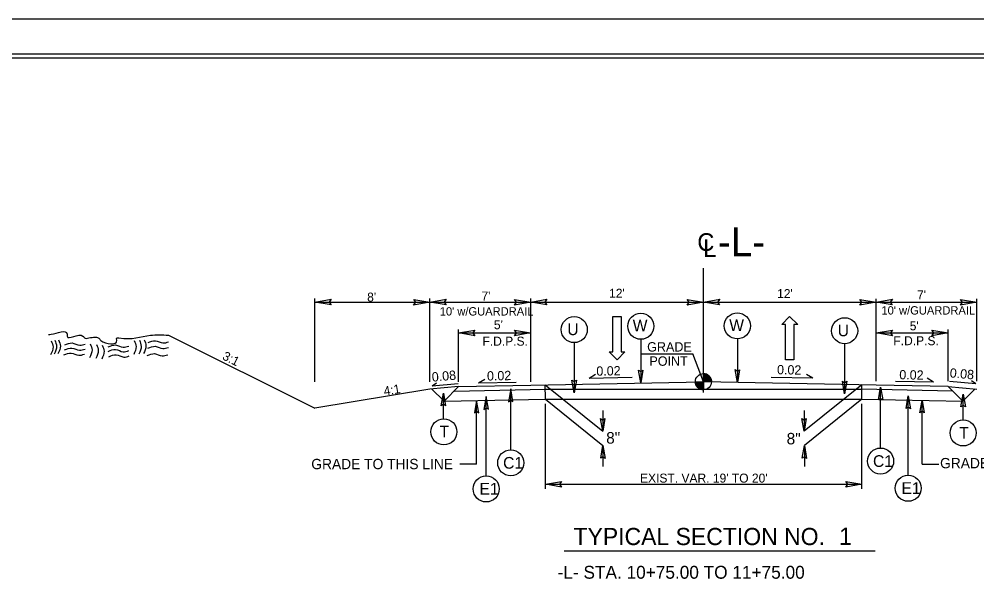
# Model space of a CAD drawing. Extents: x 1733676 to 1734289, y 540979 to 541226.
# Drawn here: x 1734169.6 to 1734236.1, y 541186.7 to 541225.9 of the extents above; entities that cross this region are included whole.
import ezdxf

# ---------------------------------------------------------------- set-up
doc = ezdxf.new("R2010")
doc.units = 0
for name, color, linetype in [('Old_Level_2', 7, 'Continuous'), ('Prop Dimension', 7, 'Continuous'), ('Prop Lane Arrow CELL', 7, 'Continuous'), ('Prop Terminator CELL', 7, 'Continuous'), ('Sheet Cutting Line CELL', 7, 'Continuous'), ('Sheet Plot Border Inside CELL', 7, 'Continuous'), ('Sheet Plot Border Outside CELL', 7, 'Continuous'), ('Sheet Typical CELL', 7, 'Continuous'), ('Typical Grade Point Symbol CELL', 7, 'Continuous'), ('Typical ID Circle CELL', 7, 'Continuous'), ('Typical Pavement Slope CELL', 7, 'Continuous'), ('Typical Pavement Slope Information CELL', 7, 'Continuous'), ('Typical Shoulder Slope CELL', 7, 'Continuous'), ('Typical Shoulder Slope Information CELL', 7, 'Continuous'), ('Typical Slope Point Local CELL', 7, 'Continuous'), ('Typical Terminator CELL', 7, 'Continuous'), ('Typical Text Centerline CELL', 7, 'Continuous'), ('Typical Text General CELL', 7, 'Continuous'), ('Typical Text Grade Point CELL', 7, 'Continuous'), ('Typical Text ID Circle CELL', 7, 'Continuous'), ('Typical Text Label CELL', 7, 'Continuous')]:
    doc.layers.add(name, color=color, linetype=linetype)

msp = doc.modelspace()

# ---------------------------------------------------------------- linework, layer by layer
at = {"layer": 'Old_Level_2'}
for points in [[(1734171.638, 541203.962), (1734171.824, 541203.984), (1734172.92, 541203.997), (1734172.922, 541203.84), (1734174.019, 541203.853), (1734174.177, 541203.698), (1734174.334, 541203.7), (1734175.117, 541203.709), (1734175.275, 541203.554), (1734176.372, 541203.567), (1734176.37, 541203.724), (1734176.526, 541203.726), (1734178.717, 541203.908), (1734179.966, 541203.922)], [(1734171.821, 541203.523), (1734171.948, 541203.104), (1734171.779, 541202.558)], [(1734172.066, 541203.561), (1734172.194, 541203.141), (1734172.024, 541202.595)], [(1734172.329, 541203.582), (1734172.456, 541203.162), (1734172.287, 541202.616)], [(1734172.749, 541202.893), (1734173.257, 541203.022), (1734173.785, 541202.87), (1734174.17, 541202.945)], [(1734172.763, 541203.245), (1734173.27, 541203.373), (1734173.798, 541203.221), (1734174.183, 541203.296)], [(1734174.525, 541203.309), (1734174.653, 541202.889), (1734174.484, 541202.343)], [(1734174.964, 541203.261), (1734175.092, 541202.842), (1734174.923, 541202.296)], [(1734175.368, 541203.213), (1734175.496, 541202.794), (1734175.327, 541202.248)], [(1734175.782, 541203.104), (1734176.289, 541203.233), (1734176.817, 541203.081), (1734177.203, 541203.155)], [(1734177.593, 541203.537), (1734177.72, 541203.118), (1734177.551, 541202.572)], [(1734177.943, 541203.559), (1734178.071, 541203.139), (1734177.902, 541202.593)], [(1734178.276, 541203.598), (1734178.404, 541203.178), (1734178.235, 541202.632)], [(1734178.538, 541203.013), (1734179.045, 541203.142), (1734179.573, 541202.99), (1734179.958, 541203.065)], [(1734178.551, 541203.399), (1734179.058, 541203.528), (1734179.586, 541203.376), (1734179.971, 541203.451)], [(1734172.701, 541202.542), (1734173.208, 541202.671), (1734173.736, 541202.519), (1734174.121, 541202.593)], [(1734175.786, 541202.788), (1734176.293, 541202.917), (1734176.821, 541202.765), (1734177.206, 541202.84)], [(1734175.825, 541202.42), (1734176.332, 541202.549), (1734176.86, 541202.397), (1734177.246, 541202.472)], [(1734178.491, 541202.504), (1734178.998, 541202.632), (1734179.526, 541202.481), (1734179.912, 541202.555)]]:
    msp.add_spline(points, degree=3, dxfattribs=at)
at = {"layer": 'Prop Dimension'}
for p, q in [((1734217.135, 541199.924), (1734217.135, 541208.57)), ((1734190.135, 541200.683), (1734190.135, 541206.461)), ((1734198.135, 541200.683), (1734198.135, 541206.461)), ((1734205.135, 541200.683), (1734205.135, 541206.461)), ((1734229.135, 541200.71), (1734229.135, 541206.434)), ((1734236.135, 541200.71), (1734236.135, 541206.434)), ((1734190.135, 541206.211), (1734198.135, 541206.211)), ((1734198.135, 541206.211), (1734205.135, 541206.211)), ((1734205.135, 541206.211), (1734217.135, 541206.211)), ((1734217.135, 541206.211), (1734229.135, 541206.211)), ((1734229.135, 541206.211), (1734236.135, 541206.211)), ((1734200.13, 541200.682), (1734200.13, 541204.32)), ((1734200.13, 541204.07), (1734205.13, 541204.07)), ((1734229.139, 541204.07), (1734234.135, 541204.07)), ((1734234.135, 541200.71), (1734234.135, 541204.32)), ((1734212.862, 541202.62), (1734216.4, 541202.62)), ((1734217.135, 541200.683), (1734216.4, 541202.62)), ((1734206.135, 541200.463), (1734210.136, 541197.239)), ((1734228.135, 541200.463), (1734224.134, 541197.239)), ((1734206.155, 541200.162), (1734228.155, 541200.162)), ((1734228.155, 541199.462), (1734228.155, 541200.143)), ((1734206.155, 541199.463), (1734228.155, 541199.462)), ((1734206.155, 541199.463), (1734210.156, 541196.24)), ((1734206.155, 541193.241), (1734206.155, 541199.146)), ((1734228.155, 541199.462), (1734224.154, 541196.239)), ((1734228.155, 541193.241), (1734228.155, 541199.146)), ((1734210.136, 541198.692), (1734210.136, 541197.239)), ((1734224.134, 541198.692), (1734224.134, 541197.239)), ((1734210.156, 541196.24), (1734210.156, 541194.787)), ((1734224.154, 541196.239), (1734224.154, 541194.786)), ((1734201.378, 541194.947), (1734200.206, 541194.947)), ((1734232.325, 541194.946), (1734233.498, 541194.946)), ((1734206.155, 541193.555), (1734228.155, 541193.555))]:
    msp.add_line(p, q, dxfattribs=at)
at = {"layer": 'Prop Lane Arrow CELL'}
for p, q in [((1734210.838, 541202.758), (1734210.838, 541205.208)), ((1734210.838, 541205.208), (1734211.416, 541205.208)), ((1734211.416, 541205.208), (1734211.416, 541202.758)), ((1734222.583, 541204.656), (1734223.126, 541205.207)), ((1734223.126, 541205.207), (1734223.686, 541204.656)), ((1734222.846, 541204.656), (1734222.583, 541204.656)), ((1734222.846, 541202.206), (1734222.846, 541204.656)), ((1734223.686, 541204.656), (1734223.423, 541204.656)), ((1734223.423, 541204.656), (1734223.423, 541202.206)), ((1734211.136, 541202.207), (1734210.576, 541202.758)), ((1734210.576, 541202.758), (1734210.838, 541202.758)), ((1734211.678, 541202.758), (1734211.136, 541202.207)), ((1734211.416, 541202.758), (1734211.678, 541202.758)), ((1734223.423, 541202.206), (1734222.846, 541202.206))]:
    msp.add_line(p, q, dxfattribs=at)
at = {"layer": 'Prop Terminator CELL'}
for points in [[(1734191.26, 541206.018), (1734190.135, 541206.211), (1734191.266, 541206.411), (1734191.122, 541206.211)], [(1734197.01, 541206.405), (1734198.135, 541206.211), (1734197.003, 541206.011), (1734197.147, 541206.211)], [(1734199.26, 541206.018), (1734198.135, 541206.211), (1734199.266, 541206.411), (1734199.122, 541206.211)], [(1734204.01, 541206.405), (1734205.135, 541206.211), (1734204.003, 541206.011), (1734204.147, 541206.211)], [(1734206.26, 541206.018), (1734205.135, 541206.211), (1734206.266, 541206.411), (1734206.122, 541206.211)], [(1734216.01, 541206.405), (1734217.135, 541206.211), (1734216.003, 541206.011), (1734216.147, 541206.211)], [(1734218.26, 541206.018), (1734217.135, 541206.211), (1734218.266, 541206.411), (1734218.122, 541206.211)], [(1734228.01, 541206.405), (1734229.135, 541206.211), (1734228.003, 541206.011), (1734228.147, 541206.211)], [(1734230.26, 541206.018), (1734229.135, 541206.211), (1734230.266, 541206.411), (1734230.122, 541206.211)], [(1734235.01, 541206.405), (1734236.135, 541206.211), (1734235.003, 541206.011), (1734235.147, 541206.211)], [(1734201.255, 541203.876), (1734200.13, 541204.07), (1734201.262, 541204.27), (1734201.118, 541204.07)], [(1734204.005, 541204.264), (1734205.13, 541204.07), (1734203.999, 541203.87), (1734204.143, 541204.07)], [(1734230.264, 541203.876), (1734229.139, 541204.07), (1734230.27, 541204.27), (1734230.127, 541204.07)], [(1734233.01, 541204.264), (1734234.135, 541204.07), (1734233.003, 541203.87), (1734233.147, 541204.07)], [(1734201.524, 541198.525), (1734201.378, 541199.369), (1734201.228, 541198.521), (1734201.378, 541198.628)], [(1734232.18, 541198.524), (1734232.325, 541199.368), (1734232.475, 541198.519), (1734232.325, 541198.627)], [(1734207.28, 541193.361), (1734206.155, 541193.555), (1734207.286, 541193.755), (1734207.142, 541193.555)], [(1734227.03, 541193.749), (1734228.155, 541193.555), (1734227.023, 541193.355), (1734227.167, 541193.555)]]:
    msp.add_lwpolyline(points, close=True, dxfattribs=at)
at = {"layer": 'Sheet Cutting Line CELL'}
msp.add_line((1734266.513, 541225.875), (1734084.641, 541225.875), dxfattribs=at)
at = {"layer": 'Sheet Plot Border Inside CELL'}
msp.add_lwpolyline([(1734266.027, 541223.451), (1734086.045, 541223.451), (1734086.045, 541109.5), (1734266.027, 541109.5)], close=True, dxfattribs=at)
at = {"layer": 'Sheet Plot Border Outside CELL'}
msp.add_lwpolyline([(1734266.513, 541225.875), (1734084.641, 541225.875), (1734084.641, 541107.075), (1734266.513, 541107.075)], close=True, dxfattribs=at)
at = {"layer": 'Sheet Typical CELL'}
msp.add_lwpolyline([(1734264.677, 541223.175), (1734102.677, 541223.175), (1734102.677, 541109.775), (1734264.677, 541109.775)], close=True, dxfattribs=at)
at = {"layer": 'Typical Grade Point Symbol CELL'}
for p, q in [((1734217.135, 541200.683), (1734217.135, 541201.242)), ((1734216.575, 541200.683), (1734217.135, 541200.683)), ((1734217.133, 541200.123), (1734217.135, 541200.683)), ((1734217.135, 541200.683), (1734217.133, 541200.123)), ((1734217.694, 541200.683), (1734217.135, 541200.683))]:
    msp.add_line(p, q, dxfattribs=at)
for points in [[(1734217.14, 541201.242), (1734217.14, 541201.242), (1734217.14, 541200.683)], [(1734217.151, 541201.242), (1734217.151, 541200.683)], [(1734217.162, 541201.241), (1734217.162, 541200.683)], [(1734217.173, 541201.241), (1734217.173, 541200.683)], [(1734217.184, 541201.24), (1734217.184, 541200.683)], [(1734217.196, 541201.238), (1734217.196, 541200.683)], [(1734217.207, 541201.237), (1734217.207, 541200.683)], [(1734217.218, 541201.236), (1734217.218, 541200.683)], [(1734217.229, 541201.235), (1734217.229, 541200.683)], [(1734217.24, 541201.232), (1734217.24, 541200.683)], [(1734217.252, 541201.23), (1734217.252, 541200.683)], [(1734217.263, 541201.227), (1734217.263, 541200.683)], [(1734217.274, 541201.225), (1734217.274, 541200.683)], [(1734217.285, 541201.221), (1734217.285, 541200.683)], [(1734217.296, 541201.218), (1734217.296, 541200.683)], [(1734217.308, 541201.215), (1734217.308, 541200.683)], [(1734217.319, 541201.211), (1734217.319, 541200.683)], [(1734217.33, 541201.207), (1734217.33, 541200.683)], [(1734217.341, 541201.202), (1734217.341, 541200.683)], [(1734217.352, 541201.197), (1734217.352, 541200.683)], [(1734217.364, 541201.192), (1734217.364, 541200.683)], [(1734217.375, 541201.187), (1734217.375, 541200.683)], [(1734217.386, 541201.182), (1734217.386, 541200.683)], [(1734217.397, 541201.176), (1734217.397, 541200.683)], [(1734217.408, 541201.17), (1734217.408, 541200.683)], [(1734217.419, 541201.164), (1734217.419, 541200.683)], [(1734217.431, 541201.158), (1734217.431, 541200.683)], [(1734217.442, 541201.15), (1734217.442, 541200.683)], [(1734217.453, 541201.143), (1734217.453, 541200.683)], [(1734217.464, 541201.134), (1734217.464, 541200.683)], [(1734217.475, 541201.126), (1734217.475, 541200.683)], [(1734217.487, 541201.118), (1734217.487, 541200.683)], [(1734217.498, 541201.108), (1734217.498, 541200.683)], [(1734217.509, 541201.098), (1734217.509, 541200.683)], [(1734217.52, 541201.088), (1734217.52, 541200.683)], [(1734217.531, 541201.077), (1734217.531, 541200.683)], [(1734217.543, 541201.066), (1734217.543, 541200.683)], [(1734217.554, 541201.053), (1734217.554, 541200.683)], [(1734217.565, 541201.039), (1734217.565, 541200.683)], [(1734217.576, 541201.026), (1734217.576, 541200.683)], [(1734217.587, 541201.011), (1734217.587, 541200.683)], [(1734216.578, 541200.683), (1734216.578, 541200.622)], [(1734216.589, 541200.683), (1734216.589, 541200.556)], [(1734216.6, 541200.683), (1734216.6, 541200.516)], [(1734216.611, 541200.683), (1734216.611, 541200.482)], [(1734216.623, 541200.683), (1734216.623, 541200.456)], [(1734216.634, 541200.683), (1734216.634, 541200.433)], [(1734216.645, 541200.683), (1734216.645, 541200.412)], [(1734216.656, 541200.683), (1734216.656, 541200.392)], [(1734216.667, 541200.683), (1734216.667, 541200.374)], [(1734216.678, 541200.683), (1734216.678, 541200.358)], [(1734216.69, 541200.683), (1734216.69, 541200.343)], [(1734216.701, 541200.683), (1734216.701, 541200.329)], [(1734216.712, 541200.683), (1734216.712, 541200.316)], [(1734216.723, 541200.683), (1734216.723, 541200.303)], [(1734216.734, 541200.683), (1734216.734, 541200.291)], [(1734216.746, 541200.683), (1734216.746, 541200.28)], [(1734216.757, 541200.683), (1734216.757, 541200.27)], [(1734216.768, 541200.683), (1734216.768, 541200.26)], [(1734216.779, 541200.683), (1734216.779, 541200.25)], [(1734216.79, 541200.683), (1734216.79, 541200.241)], [(1734216.802, 541200.683), (1734216.802, 541200.233)], [(1734216.813, 541200.683), (1734216.813, 541200.225)], [(1734216.824, 541200.683), (1734216.824, 541200.218)], [(1734216.835, 541200.683), (1734216.835, 541200.21)], [(1734216.846, 541200.683), (1734216.846, 541200.203)], [(1734216.857, 541200.683), (1734216.857, 541200.196)], [(1734216.869, 541200.683), (1734216.869, 541200.19)], [(1734216.88, 541200.683), (1734216.88, 541200.184)], [(1734216.891, 541200.683), (1734216.891, 541200.179)], [(1734216.902, 541200.683), (1734216.902, 541200.174)], [(1734216.913, 541200.683), (1734216.913, 541200.169)], [(1734216.925, 541200.683), (1734216.925, 541200.164)], [(1734216.936, 541200.683), (1734216.936, 541200.159)], [(1734216.947, 541200.683), (1734216.947, 541200.155)], [(1734216.958, 541200.683), (1734216.958, 541200.152)], [(1734216.969, 541200.683), (1734216.969, 541200.148)], [(1734216.981, 541200.683), (1734216.981, 541200.145)], [(1734216.992, 541200.683), (1734216.992, 541200.142)], [(1734217.003, 541200.683), (1734217.003, 541200.139)], [(1734217.014, 541200.683), (1734217.014, 541200.137)], [(1734217.025, 541200.683), (1734217.025, 541200.134)], [(1734217.036, 541200.683), (1734217.036, 541200.132)], [(1734217.048, 541200.683), (1734217.048, 541200.131)], [(1734217.059, 541200.683), (1734217.059, 541200.128)], [(1734217.07, 541200.683), (1734217.07, 541200.127)], [(1734217.081, 541200.683), (1734217.081, 541200.126)], [(1734217.092, 541200.683), (1734217.092, 541200.124)], [(1734217.104, 541200.683), (1734217.104, 541200.124)], [(1734217.115, 541200.683), (1734217.115, 541200.123)], [(1734217.126, 541200.683), (1734217.126, 541200.123), (1734217.126, 541200.123)], [(1734217.599, 541200.995), (1734217.599, 541200.683)], [(1734217.61, 541200.977), (1734217.61, 541200.683)], [(1734217.621, 541200.959), (1734217.621, 541200.683)], [(1734217.632, 541200.939), (1734217.632, 541200.683)], [(1734217.643, 541200.915), (1734217.643, 541200.683)], [(1734217.654, 541200.889), (1734217.654, 541200.683)], [(1734217.666, 541200.858), (1734217.666, 541200.683)], [(1734217.677, 541200.819), (1734217.677, 541200.683)], [(1734217.688, 541200.762), (1734217.688, 541200.683)]]:
    msp.add_lwpolyline(points, dxfattribs=at)
msp.add_circle((1734217.134, 541200.683), 0.559, dxfattribs=at)
for start, end in [(359.99048, 89.99048), (179.99048, 269.99048)]:
    msp.add_arc((1734217.134, 541200.683), 0.559, start, end, dxfattribs=at)
at = {"layer": 'Typical ID Circle CELL'}
for p, q in [((1734208.16, 541203.396), (1734208.16, 541199.914)), ((1734212.786, 541203.63), (1734212.786, 541200.609)), ((1734219.493, 541203.656), (1734219.493, 541200.636)), ((1734226.949, 541203.316), (1734226.949, 541199.834)), ((1734199.068, 541198.102), (1734199.068, 541199.882)), ((1734203.748, 541195.951), (1734203.748, 541200.178)), ((1734229.449, 541196.073), (1734229.449, 541200.298)), ((1734231.365, 541194.186), (1734231.365, 541199.692)), ((1734235.181, 541198.029), (1734235.181, 541199.808)), ((1734201.378, 541194.947), (1734201.378, 541199.369)), ((1734202.043, 541194.139), (1734202.043, 541199.644)), ((1734232.325, 541194.946), (1734232.325, 541199.368))]:
    msp.add_line(p, q, dxfattribs=at)
for centre in [(1734208.16, 541204.303), (1734212.786, 541204.536), (1734219.493, 541204.563), (1734226.949, 541204.222), (1734199.101, 541197.197), (1734235.181, 541197.123), (1734203.748, 541195.045), (1734229.449, 541195.167), (1734202.043, 541193.232), (1734231.365, 541193.279)]:
    msp.add_circle(centre, 0.906, dxfattribs=at)
at = {"layer": 'Typical Pavement Slope CELL'}
for p, q in [((1734200.13, 541200.34), (1734198.13, 541200.173)), ((1734205.135, 541200.443), (1734217.135, 541200.683)), ((1734206.155, 541199.463), (1734206.135, 541200.463)), ((1734229.135, 541200.443), (1734217.135, 541200.683)), ((1734228.155, 541199.462), (1734228.155, 541200.462)), ((1734234.135, 541200.34), (1734236.135, 541200.173)), ((1734199.112, 541199.322), (1734206.155, 541199.463)), ((1734228.155, 541199.462), (1734235.153, 541199.322))]:
    msp.add_line(p, q, dxfattribs=at)
at = {"layer": 'Typical Pavement Slope Information CELL'}
for p, q in [((1734209.202, 541200.939), (1734209.639, 541201.203)), ((1734209.202, 541200.939), (1734212.193, 541200.999)), ((1734224.745, 541200.917), (1734224.296, 541201.189)), ((1734198.293, 541200.394), (1734198.585, 541200.599)), ((1734198.293, 541200.394), (1734200.101, 541200.556)), ((1734201.518, 541200.596), (1734201.956, 541200.86)), ((1734201.518, 541200.596), (1734204.118, 541200.648)), ((1734224.745, 541200.917), (1734221.851, 541200.975)), ((1734233.133, 541200.646), (1734230.493, 541200.699)), ((1734233.133, 541200.646), (1734232.684, 541200.918)), ((1734236.066, 541200.542), (1734234.228, 541200.697)), ((1734236.066, 541200.542), (1734235.765, 541200.752))]:
    msp.add_line(p, q, dxfattribs=at)
at = {"layer": 'Typical Shoulder Slope CELL'}
for p, q in [((1734200.13, 541200.34), (1734199.112, 541199.321)), ((1734200.13, 541200.34), (1734205.135, 541200.443)), ((1734234.135, 541200.34), (1734229.135, 541200.443)), ((1734234.135, 541200.34), (1734235.153, 541199.321)), ((1734198.25, 541200.183), (1734199.112, 541199.321)), ((1734199.824, 541200.034), (1734206.155, 541200.163)), ((1734234.441, 541200.034), (1734228.155, 541200.163)), ((1734236.015, 541200.183), (1734235.153, 541199.321))]:
    msp.add_line(p, q, dxfattribs=at)
at = {"layer": 'Typical Slope Point Local CELL'}
for p in [(1734179.966, 541203.922), (1734198.13, 541200.173)]:
    msp.add_line(p, (1734190.13, 541198.84), dxfattribs=at)
at = {"layer": 'Typical Terminator CELL'}
for points in [[(1734212.938, 541201.488), (1734212.786, 541200.609), (1734212.63, 541201.493), (1734212.786, 541201.381)], [(1734219.644, 541201.515), (1734219.493, 541200.636), (1734219.337, 541201.52), (1734219.493, 541201.407)], [(1734208.312, 541200.793), (1734208.16, 541199.914), (1734208.004, 541200.798), (1734208.16, 541200.686)], [(1734227.1, 541200.713), (1734226.949, 541199.834), (1734226.793, 541200.718), (1734226.949, 541200.605)], [(1734198.917, 541199.003), (1734199.068, 541199.882), (1734199.224, 541198.998), (1734199.068, 541199.111)], [(1734203.9, 541199.299), (1734203.748, 541200.178), (1734203.592, 541199.294), (1734203.748, 541199.407)], [(1734229.298, 541199.419), (1734229.449, 541200.298), (1734229.605, 541199.414), (1734229.449, 541199.526)], [(1734231.213, 541198.813), (1734231.365, 541199.692), (1734231.521, 541198.808), (1734231.365, 541198.92)], [(1734235.03, 541198.93), (1734235.181, 541199.808), (1734235.337, 541198.925), (1734235.181, 541199.037)], [(1734202.195, 541198.766), (1734202.043, 541199.644), (1734201.887, 541198.761), (1734202.043, 541198.873)], [(1734210.287, 541198.118), (1734210.136, 541197.239), (1734209.98, 541198.123), (1734210.136, 541198.011)], [(1734224.285, 541198.118), (1734224.134, 541197.239), (1734223.977, 541198.123), (1734224.134, 541198.011)], [(1734210.005, 541195.361), (1734210.156, 541196.24), (1734210.312, 541195.356), (1734210.156, 541195.468)], [(1734224.002, 541195.36), (1734224.154, 541196.239), (1734224.31, 541195.355), (1734224.154, 541195.467)]]:
    msp.add_lwpolyline(points, close=True, dxfattribs=at)
at = {"layer": 'Typical Text Label CELL'}
msp.add_line((1734207.469, 541188.929), (1734229.073, 541188.929), dxfattribs=at)

# ---------------------------------------------------------------- texts
at = {"layer": 'Typical Pavement Slope Information CELL'}
for rotation, p in [(1.14574, (1734209.703, 541201.094)), (358.85426, (1734222.248, 541201.202))]:
    msp.add_text('0.02', height=0.6476, rotation=rotation, dxfattribs=at).set_placement(p)
at = {"layer": 'Typical Shoulder Slope Information CELL'}
for s, rotation, p in [('0.08', 5.10489, (1734198.293, 541200.68)), ('0.02', 1.14574, (1734202.103, 541200.76)), ('0.02', 358.85426, (1734230.742, 541200.852)), ('0.08', 355.18719, (1734234.232, 541200.982))]:
    msp.add_text(s, height=0.6476, rotation=rotation, dxfattribs=at).set_placement(p)
at = {"layer": 'Typical Slope Point Local CELL'}
for s, height, rotation, p in [("12'", 0.6249, 360, (1734210.581, 541206.516)), ("12'", 0.6249, 360, (1734222.255, 541206.49)), ("7'", 0.6249, 360, (1734231.982, 541206.412)), ("8'", 0.6249, 360, (1734193.772, 541206.249)), ("7'", 0.6249, 360, (1734201.715, 541206.325)), ("10' w/GUARDRAIL", 0.57868, 360, (1734198.814, 541205.282)), ("10' w/GUARDRAIL", 0.57868, 360, (1734229.505, 541205.349)), ("5'", 0.6249, 360, (1734202.576, 541204.329)), ("5'", 0.6249, 360, (1734231.473, 541204.252)), ('F.D.P.S.', 0.6249, 360, (1734201.785, 541203.186)), ('F.D.P.S.', 0.6249, 360, (1734230.336, 541203.219)), ('3:1', 0.6249, 333.43495, (1734183.659, 541202.265)), ('4:1', 0.6249, 9.46232, (1734194.972, 541199.71)), ('8"', 0.8, 360, (1734210.379, 541196.379)), ('8"', 0.8, 360, (1734222.92, 541196.326)), ("EXIST. VAR. 19' TO 20'", 0.6249, 360, (1734212.731, 541193.671))]:
    msp.add_text(s, height=height, rotation=rotation, dxfattribs=at).set_placement(p)
at = {"layer": 'Typical Text Centerline CELL'}
for s, height, p in [('C', 1.23, (1734216.711, 541209.77)), ('-L-', 2, (1734218.148, 541209.404))]:
    msp.add_text(s, height=height, dxfattribs=at).set_placement(p)
msp.add_text('L', height=1.231, rotation=359.9469, dxfattribs=at).set_placement((1734217.12, 541209.35))
at = {"layer": 'Typical Text General CELL'}
for p in [(1734189.892, 541194.604), (1734233.581, 541194.667)]:
    msp.add_text('GRADE TO THIS LINE', height=0.71614, dxfattribs=at).set_placement(p)
at = {"layer": 'Typical Text Grade Point CELL'}
for s, p in [('GRADE', (1734213.226, 541202.777)), ('POINT', (1734213.383, 541201.788))]:
    msp.add_text(s, height=0.6525, dxfattribs=at).set_placement(p)
at = {"layer": 'Typical Text ID Circle CELL'}
for s, height, p in [('W', 0.811, (1734218.932, 541204.203)), ('U', 0.811, (1734207.679, 541203.92)), ('W', 0.811, (1734212.225, 541204.177)), ('U', 0.811, (1734226.467, 541203.839)), ('T', 0.811, (1734198.808, 541196.806)), ('T', 0.811, (1734234.914, 541196.717)), ('C1', 0.8112, (1734203.22, 541194.639)), ('C1', 0.8112, (1734228.92, 541194.761)), ('E1', 0.8112, (1734230.899, 541192.889)), ('E1', 0.8112, (1734201.578, 541192.842))]:
    msp.add_text(s, height=height, dxfattribs=at).set_placement(p)
at = {"layer": 'Typical Text Label CELL'}
for s, height, p in [('TYPICAL SECTION NO.  ', 1.19356, (1734208.109, 541189.329)), ('1', 1.194, (1734226.562, 541189.345)), ('-L- STA. 10+75.00 TO 11+75.00', 0.89517, (1734207.007, 541186.992))]:
    msp.add_text(s, height=height, dxfattribs=at).set_placement(p)

doc.saveas('drawing.dxf')
